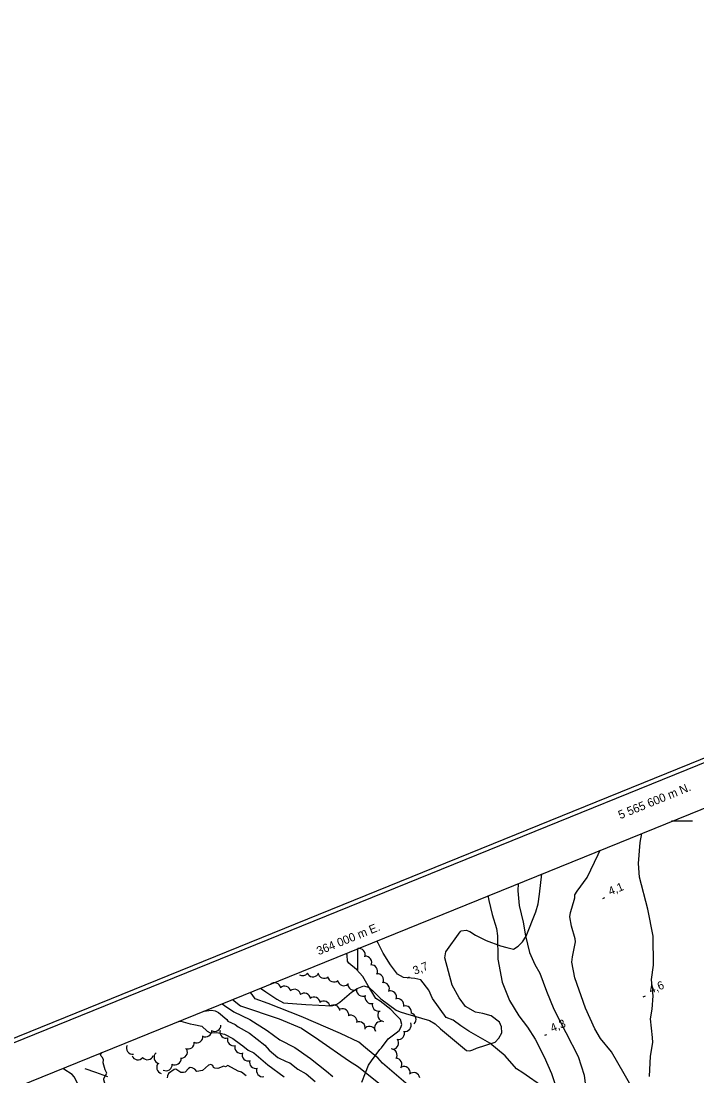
# Model space of a CAD drawing. Extents: x 362852 to 366875, y 5563573 to 5566479.
# Drawn here: x 363840.5 to 364160.7, y 5565479.3 to 5565979.3 of the extents above; entities that cross this region are included whole.
import ezdxf

# ---------------------------------------------------------------- set-up
doc = ezdxf.new("R2010")
doc.units = 0
for name, color, linetype in [('Niveau 1', 7, 'Continuous'), ('Niveau 2', 7, 'Continuous'), ('Niveau 22', 7, 'Continuous'), ('Niveau 3', 7, 'Continuous'), ('Niveau 44', 7, 'Continuous'), ('Niveau 60', 7, 'Continuous'), ('Niveau 61', 7, 'Continuous'), ('Niveau 7', 7, 'Continuous')]:
    doc.layers.add(name, color=color, linetype=linetype)

msp = doc.modelspace()

# ---------------------------------------------------------------- linework, layer by layer
at = {"layer": 'Niveau 1'}
for points in [[(363935.72, 5565513.56), (363936.82, 5565512.62)], [(363936.82, 5565512.62), (363941.35, 5565509.71), (363948.91, 5565506.06), (363957.11, 5565500.86), (363963.15, 5565496.42), (363970.17, 5565492.8), (363977.67, 5565487.57), (363985.18, 5565481.63), (363988.24, 5565478.98)]]:
    msp.add_lwpolyline(points, dxfattribs=at)
at = {"layer": 'Niveau 2'}
for points in [[(363954, 5565520.98), (363956.4, 5565519.15), (363961.7, 5565515.65), (363964.9, 5565513.94), (363975.46, 5565513.24), (363987.74, 5565512.61), (363990.08, 5565513.32), (363991.6, 5565514.2), (363997.06, 5565518.96), (363999.75, 5565520.7), (364002.82, 5565522.08), (364005.41, 5565521.26), (364007.79, 5565519.09), (364010.98, 5565515.86), (364018.27, 5565510.53), (364020.13, 5565509.66), (364022.68, 5565508.94), (364033.96, 5565505.51), (364036.71, 5565503.99), (364039.28, 5565501.65), (364051.6, 5565491.33), (364053.05, 5565491.17), (364054.49, 5565491.64), (364056.27, 5565492.49), (364065.16, 5565495.27), (364066.87, 5565497.23), (364068.26, 5565499.69), (364068.07, 5565502.64), (364067.19, 5565504.8), (364063.26, 5565507.72), (364059.29, 5565508.86), (364055.86, 5565509.59), (364051.06, 5565512.16), (364048.1, 5565516.36), (364044.81, 5565522.32), (364041.33, 5565535.26), (364041.81, 5565538.11), (364048.51, 5565547.55), (364049.07, 5565548.03), (364051.33, 5565548.33), (364053.05, 5565547.78), (364055.73, 5565546.1), (364060.9, 5565543.56), (364067.68, 5565541.05), (364070.63, 5565540.25), (364073.85, 5565539.42), (364076.04, 5565540.83), (364078.11, 5565542.82), (364079.88, 5565545.56), (364084.36, 5565557.11), (364085.48, 5565560.85), (364086.09, 5565565.52), (364087.31, 5565575.08)], [(363940.59, 5565515.53), (363944.52, 5565512.57), (363962.77, 5565506.37), (363973.43, 5565501.95), (363981.56, 5565496.37), (363995.64, 5565486.58)], [(364030.49, 5565469.27), (364011.72, 5565485.34), (364009.47, 5565487.81), (364007.33, 5565489.7), (364003.61, 5565492.7), (364000.54, 5565495.34), (363991.91, 5565499.35), (363973.21, 5565507.52), (363957.58, 5565513.69), (363951.46, 5565515.83), (363949.96, 5565517.98), (363949.07, 5565518.98)], [(363926.94, 5565509.99), (363927.02, 5565509.98), (363930.72, 5565510.53), (363932.43, 5565510.12), (363934.06, 5565509.36), (363937.99, 5565506.08), (363938.4, 5565505.33), (363941.85, 5565503.69), (363943.27, 5565502.51), (363948.65, 5565499.65), (363955.96, 5565493.82), (363958.03, 5565491.6), (363962.22, 5565488.04), (363966.1, 5565486.16), (363967.89, 5565485.46), (363971.58, 5565482.45), (363975.54, 5565480.25), (363979.89, 5565476.73)], [(363915.13, 5565505.2), (363915.21, 5565505.15), (363916.22, 5565505.27), (363920.61, 5565504.08), (363922.32, 5565503.69), (363926.09, 5565502.83), (363928.68, 5565500.57), (363930.15, 5565499.76), (363933.25, 5565499.94), (363936.84, 5565499.07), (363940.79, 5565497.03), (363944.38, 5565494.36), (363945.48, 5565493.61), (363948.16, 5565491.57), (363950.84, 5565490.23), (363957.42, 5565484.54), (363965.21, 5565478.85)], [(363886.25, 5565465.22), (363885.87, 5565466.51), (363883.87, 5565468.59), (363883.01, 5565470.28), (363882.2, 5565471.28), (363881.6, 5565473.41), (363880.37, 5565475.17), (363879.72, 5565477.44), (363879.7, 5565478.14), (363881.08, 5565480.66), (363880.29, 5565482.19), (363879.35, 5565485.44), (363879.47, 5565486.9), (363879.14, 5565488.04), (363878.4, 5565488.71), (363878.17, 5565489.52), (363878.75, 5565490.43)], [(363995.64, 5565486.58), (364000.34, 5565483.61), (364010.74, 5565475.2)], [(363867.39, 5565475.64), (363865.59, 5565478.84), (363864.73, 5565479.98), (363864.73, 5565479.98), (363860.67, 5565482.51), (363860.29, 5565482.94)], [(363913.01, 5565482.29), (363910.37, 5565480.45), (363909.79, 5565479.42), (363909.74, 5565478.36)], [(363947.14, 5565479.28), (363944.85, 5565481.08), (363943.34, 5565481.52), (363938.51, 5565484.18), (363937.42, 5565483.7), (363936.63, 5565484), (363933.79, 5565482.82), (363932.35, 5565482.95), (363931.72, 5565483.29), (363931.28, 5565484.22), (363930.44, 5565484.69), (363929.31, 5565484.37), (363926.48, 5565481.96), (363923.84, 5565481.36), (363922.79, 5565482.49), (363921.55, 5565483.16), (363920.65, 5565483.26), (363919.87, 5565482.87), (363918.25, 5565481.16), (363917.44, 5565480.94), (363916.23, 5565480.92), (363913.81, 5565482.53), (363913.01, 5565482.29)]]:
    msp.add_lwpolyline(points, dxfattribs=at)
at = {"layer": 'Niveau 22'}
for points in [[(364138.2, 5565478.97), (364138.69, 5565488.74), (364139.77, 5565495.22), (364139.74, 5565497.6), (364138.72, 5565506.31), (364139.59, 5565510.95), (364139.93, 5565517.27), (364139.4, 5565523.22), (364139.2, 5565525.08), (364140.21, 5565531.87), (364140.06, 5565545.54), (364137.48, 5565558.28), (364133.48, 5565573.6), (364133.02, 5565580.03), (364133.8, 5565590), (364134.65, 5565594.3)], [(364134.57, 5565467.62), (364129.45, 5565474.84), (364126.18, 5565480.29), (364120.27, 5565490.7), (364114.99, 5565497.09), (364112.39, 5565501.63), (364107.86, 5565511.42), (364102.92, 5565525.77), (364101.49, 5565533.31), (364101.83, 5565535.72), (364103.26, 5565542.86), (364103.01, 5565544.27), (364101.37, 5565550.35), (364100.43, 5565554.69), (364100.77, 5565556.78), (364101.53, 5565558.8), (364102.86, 5565563.69), (364102.91, 5565565.1), (364103.94, 5565566.91), (364108.75, 5565573.3), (364113.88, 5565584.31), (364114.87, 5565586.27)], [(364076.01, 5565570.5), (364075.83, 5565567.1), (364076.49, 5565560.05), (364078.35, 5565552.24), (364079.56, 5565545.67), (364081.42, 5565537.86), (364083.93, 5565532.08), (364086.33, 5565528.03), (364089.46, 5565519.54), (364092.91, 5565510.88), (364098.61, 5565499.93), (364104.42, 5565488.53), (364107.28, 5565479.75), (364107.85, 5565475.71), (364109.14, 5565466.36), (364112.07, 5565454.65), (364113.52, 5565446.25), (364113.89, 5565439.48), (364113.44, 5565436.4), (364113.34, 5565434.35), (364113.24, 5565432.11), (364114.15, 5565428.76), (364115.31, 5565425.58), (364116.62, 5565422.98)], [(364061.87, 5565564.76), (364061.88, 5565564.09), (364062.07, 5565562.53), (364063.68, 5565555.81), (364065.7, 5565549.13), (364066.22, 5565545.69), (364066.44, 5565534.62), (364068.52, 5565523.75), (364071.94, 5565515.13), (364076.3, 5565507.78), (364080.48, 5565502.44), (364084.06, 5565496.73), (364088.34, 5565488.35), (364091.81, 5565480.39), (364094.33, 5565472.93)], [(364001.91, 5565476.42), (364003.62, 5565480.73), (364005.13, 5565484.43), (364006.6, 5565486.44), (364010.5, 5565491.77), (364011.19, 5565492.68), (364014.46, 5565496.91), (364018.28, 5565499.68), (364019.6, 5565500.92), (364020.36, 5565502.23), (364020.83, 5565503.68), (364020.31, 5565506.05), (364017.92, 5565508.41), (364015.63, 5565510.74), (364010.69, 5565514.69), (364008.63, 5565516.05), (364007.09, 5565518.32), (364004.91, 5565522.08), (364002.4, 5565526.48), (363999.36, 5565529.76), (363995.78, 5565532.71), (363995.23, 5565533.75), (363994.92, 5565536.52), (363994.68, 5565537.49)], [(363870.69, 5565482.87), (363875.69, 5565481.04), (363879.16, 5565479.83), (363881.37, 5565479.11)]]:
    msp.add_lwpolyline(points, dxfattribs=at)
at = {"layer": 'Niveau 3'}
for p, q in [((364116.14, 5565563.46), (364117.1, 5565563.85)), ((364023.54, 5565525.83), (364024.5, 5565526.22)), ((364135.33, 5565516.83), (364136.29, 5565517.22)), ((364088.67, 5565498.62), (364089.63, 5565499.01))]:
    msp.add_line(p, q, dxfattribs=at)
at = {"layer": 'Niveau 44'}
for centre, start, end in [((364000.53, 5565536.79), 340.6491, 100.627), ((364003.63, 5565533.1), 333.7809, 93.7589), ((364006.41, 5565528.94), 333.7809, 93.7589), ((363973.82, 5565529.83), 240.5235, 323.2607), ((363978.77, 5565529.28), 204.0245, 324.0025), ((363984.1, 5565528.6), 189.2804, 309.2584), ((363988.77, 5565526.83), 189.2804, 309.2584), ((364009.19, 5565524.79), 333.7809, 93.7589), ((363960.6, 5565520.46), 12.0966, 132.0746), ((363965.35, 5565518.92), 12.0966, 132.0746), ((363970, 5565517.38), 8.1784, 128.1564), ((363993.45, 5565525.06), 189.2804, 309.2584), ((363998.31, 5565522.88), 175.7242, 295.7021), ((364002.44, 5565520.06), 175.7242, 295.7021), ((364011.99, 5565520.64), 334.0959, 94.0739), ((363974.64, 5565515.52), 8.1784, 128.1564), ((363979.28, 5565513.66), 8.1784, 128.1564), ((364006.44, 5565516.59), 163.5619, 283.5398), ((364015.37, 5565516.66), 342.739, 102.717), ((364018.87, 5565512.95), 346.5797, 106.5577), ((363983.93, 5565511.79), 8.3404, 128.3183), ((363988.57, 5565509.95), 8.3404, 128.3183), ((363992.76, 5565508.17), 351.7479, 111.7258), ((364009.88, 5565512.97), 163.5619, 283.5398), ((364022.5, 5565509.52), 346.5797, 106.5577), ((363996.68, 5565505.07), 351.7479, 111.7258), ((364012.49, 5565508.17), 143.596, 263.574), ((364024.64, 5565506.16), 314.6243, 74.6023), ((363927.92, 5565500.82), 241.0118, 0.9897), ((363932.2, 5565503.39), 241.0118, 0.9897), ((363937.67, 5565500.17), 166.3015, 286.2794), ((364000.61, 5565501.98), 351.7479, 111.7258), ((364005.61, 5565499.82), 10.0306, 130.0085), ((364010.94, 5565502.08), 87.6786, 207.6566), ((364019.16, 5565499.53), 260.612, 20.5899), ((364022.34, 5565503.39), 260.612, 20.5899), ((363919.59, 5565495.07), 245.6062, 5.5841), ((363923.66, 5565497.98), 245.6062, 5.5841), ((363941.22, 5565496.57), 164.4521, 284.43), ((364016.39, 5565494.95), 275.8269, 35.8049), ((363893.42, 5565492.55), 155.1528, 275.1308), ((363906.51, 5565488.12), 134.2348, 254.2128), ((363916.28, 5565490.7), 265.4505, 25.4285), ((363944.72, 5565493), 164.4521, 284.43), ((363948.22, 5565489.43), 164.4521, 284.43), ((364015.64, 5565489.12), 327.5685, 87.5465), ((363895.87, 5565489.97), 200.8278, 320.8057), ((363900.33, 5565490), 219.5562, 339.5342), ((363907.74, 5565483.28), 134.2348, 254.2128), ((363913.33, 5565487.51), 243.3572, 3.3351), ((363951.72, 5565485.86), 164.4521, 284.43), ((364017.95, 5565484.69), 327.5685, 87.5465), ((363909.15, 5565484.77), 243.3572, 3.3351), ((363955.01, 5565481.93), 159.5966, 279.5745), ((364021.9, 5565480.78), 353.0437, 113.0217), ((364026.5, 5565477.88), 11.4197, 131.3976)]:
    msp.add_arc(centre, 3, start, end, dxfattribs=at)
at = {"layer": 'Niveau 60'}
for points in [[(363470.95, 5563573.17), (366875.21, 5564954.96), (366256.48, 5566479.3), (362852.22, 5565097.5), (363470.95, 5563573.17)], [(363472.05, 5563575.77), (366872.61, 5564956.04), (366255.38, 5566476.69), (362854.83, 5565096.41), (363472.05, 5563575.77)], [(362880.89, 5565085.4), (365762.56, 5566255.07), (366364.73, 5564771.5), (366364.73, 5564771.5), (363483.08, 5563601.82), (362880.89, 5565085.4)]]:
    msp.add_lwpolyline(points, dxfattribs=at)
at = {"layer": 'Niveau 61'}
for points in [[(364158.69, 5565600), (364148.69, 5565600)], [(364000, 5565529.65), (364000, 5565539.65)]]:
    msp.add_lwpolyline(points, dxfattribs=at)
at = {"layer": 'Niveau 7'}
msp.add_lwpolyline([(364091.35, 5565471.75), (364088.24, 5565473.87), (364078.25, 5565480.83), (364075.22, 5565482.74), (364069.87, 5565488.85), (364062.53, 5565494.91), (364052.69, 5565500.55), (364048.82, 5565502.99), (364045.22, 5565505.68), (364041.94, 5565506.97), (364035.37, 5565515.98), (364033.75, 5565519.98), (364029.9, 5565524.83), (364027.1, 5565525.57), (364021.67, 5565525.99), (364018.92, 5565527.51), (364015.51, 5565531.91), (364011.98, 5565537.52), (364009.69, 5565542.26), (364009.01, 5565543.3)], dxfattribs=at)

# ---------------------------------------------------------------- texts
at = {"layer": 'Niveau 3'}
for s, p in [('4,1  ', (364119.65, 5565564.82)), ('3,7  ', (364027.05, 5565527.19)), ('4,6  ', (364138.84, 5565518.19)), ('4,3  ', (364092.18, 5565499.98))]:
    msp.add_text(s, height=3.93, rotation=22.09, dxfattribs=at).set_placement(p)
at = {"layer": 'Niveau 61'}
for s, p in [('5 565 600 m N.', (364124.41, 5565600.96)), ('364 000 m E.', (363981.5, 5565536.47))]:
    msp.add_text(s, height=4, rotation=22.0922, dxfattribs=at).set_placement(p)

doc.saveas('drawing.dxf')
